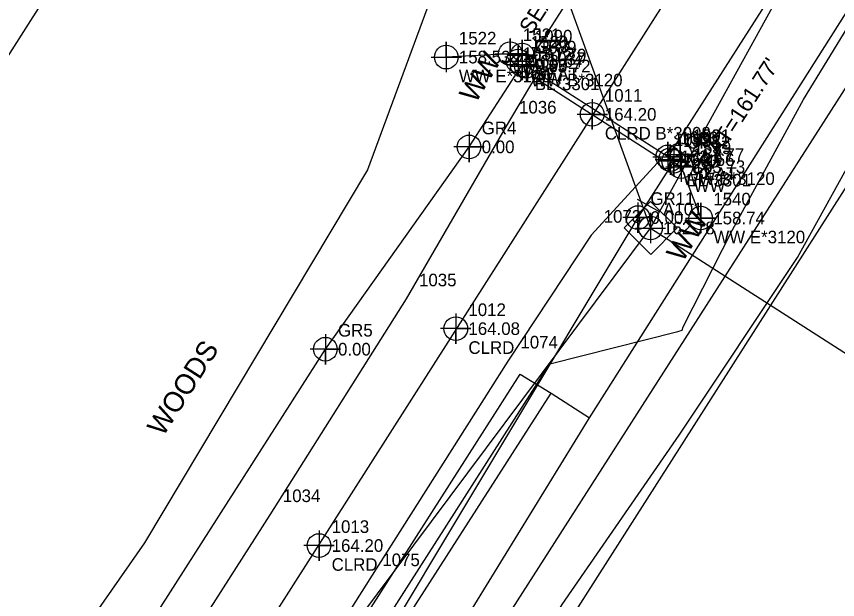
# Model space of a CAD drawing. Extents: x 1840200 to 1849051, y 348278 to 353012.
# Drawn here: x 1844547 to 1844709.8, y 350604.9 to 350720.4 of the extents above; entities that cross this region are included whole.
import ezdxf

# ---------------------------------------------------------------- set-up
doc = ezdxf.new("R2010")
doc.units = 0
for name, color, linetype in [('Cogo Default Point CELL', 7, 'Continuous'), ('COGO Default Point Elevation', 7, 'Continuous'), ('COGO Default Point Number', 7, 'Continuous'), ('CTL Supplemental Horizontal and Vertical CELL', 7, 'Continuous'), ('Exist DTM Crownline Cogo Comment', 7, 'Continuous'), ('Exist DTM Crownline Cogo Elevation', 7, 'Continuous'), ('Exist DTM Crownline Cogo Number', 7, 'Continuous'), ('Exist DTM Crownline Cogo Point CELL', 7, 'Continuous'), ('Exist Guardrail', 7, 'Continuous'), ('Exist Guardrail Cogo Comment', 7, 'Continuous'), ('Exist Guardrail Cogo Elevation', 7, 'Continuous'), ('Exist Guardrail Cogo Number', 7, 'Continuous'), ('Exist Guardrail Cogo Point CELL', 7, 'Continuous'), ('Exist Horizontal Alignment', 7, 'Continuous'), ('Exist Horizontal Baseline Alignment', 7, 'Continuous'), ('Exist Horizontal Baseline Alignment Station Label', 7, 'Continuous'), ('Exist Horizontal Baseline Alignment Tick small', 7, 'Continuous'), ('Exist Horizontal T-Line Alignment', 7, 'Continuous'), ('Exist Right of Way Line', 7, 'Continuous'), ('Exist Roads EOP', 7, 'Continuous'), ('Exist Roads EOP Cogo Number', 7, 'Continuous'), ('Exist Structure Major Bridge Seat Cogo Comment', 7, 'Continuous'), ('Exist Structure Major Bridge Seat Cogo Elevation', 7, 'Continuous'), ('Exist Structure Major Bridge Seat Cogo Number', 7, 'Continuous'), ('Exist Structure Major Bridge Seat Cogo Point CELL', 7, 'Continuous'), ('Exist Structure Major Bridge Seat Top Elevation', 7, 'Continuous'), ('Exist Structure Major Deck Tunnel Box Culvert', 7, 'Continuous'), ('Exist Structure Major Deck Tunnel Box Culvert Cogo Elevation', 7, 'Continuous'), ('Exist Structure Major Deck Tunnel Box Culvert Cogo Number', 7, 'Continuous'), ('Exist Structure Major Deck Tunnel Box Culvert Cogo Point CELL', 7, 'Continuous'), ('Exist Structure Minor Head and End Wall', 7, 'Continuous'), ('Exist Structure Minor Head and End Wall Cogo Comment', 7, 'Continuous'), ('Exist Structure Minor Head and End Wall Cogo Elevation', 7, 'Continuous'), ('Exist Structure Minor Head and End Wall Cogo Number', 7, 'Continuous'), ('Exist Structure Minor Head and End Wall Cogo Point CELL', 7, 'Continuous'), ('Exist Structure Minor Head and End Wall Text', 7, 'Continuous'), ('Exist Utilities Telephone UG Cable', 7, 'Continuous'), ('Exist Utilities Water UG Line SUE', 7, 'Continuous'), ('Exist Vegetation Woods Line', 7, 'Continuous'), ('Exist Vegetation Woods Line Text', 7, 'Continuous')]:
    doc.layers.add(name, color=color, linetype=linetype)

# ---------------------------------------------------------------- blocks, each defined once
blk = doc.blocks.new('EXIST DTM CROWNLINE COGO POINT')
at = {"layer": 'Exist DTM Crownline Cogo Point CELL'}
blk.add_lwpolyline([(0, 0.06), (0, -0.06), (0, 0), (0.06, 0), (-0.06, 0)], dxfattribs=at)
blk.add_circle((0, 0), 0.0469, dxfattribs=at)
blk = doc.blocks.new('EXIST STRUCTURE MAJOR BRIDGE SEAT COGO POINT')
at = {"layer": 'Exist Structure Major Bridge Seat Cogo Point CELL'}
blk.add_lwpolyline([(-0.06, 0), (0.06, 0), (0, 0), (0, 0.06), (0, -0.06)], dxfattribs=at)
blk.add_circle((0, 0), 0.0469, dxfattribs=at)
blk = doc.blocks.new('EXIST STRUCTURE MINOR HEAD AND END WALL COGO POINT')
at = {"layer": 'Exist Structure Minor Head and End Wall Cogo Point CELL'}
blk.add_lwpolyline([(-0.06, 0), (0.06, 0), (0, 0), (0, 0.06), (0, -0.06)], dxfattribs=at)
blk.add_circle((0, 0), 0.0469, dxfattribs=at)
blk = doc.blocks.new('EXIST STRUCTURE MAJOR DECK TUNNEL BOX CULVERT COGO POINT')
at = {"layer": 'Exist Structure Major Deck Tunnel Box Culvert Cogo Point CELL'}
blk.add_lwpolyline([(-0.06, 0), (0.06, 0), (0, 0), (0, 0.06), (0, -0.06)], dxfattribs=at)
blk.add_circle((0, 0), 0.0469, dxfattribs=at)
blk = doc.blocks.new('COGO DEFAULT POINT')
at = {"layer": 'Cogo Default Point CELL'}
for points in [[(0, 0.06), (0, 0)], [(-0.06, 0), (0, 0)], [(0, 0), (0.06, 0)], [(0, 0), (0, -0.06)]]:
    blk.add_lwpolyline(points, dxfattribs=at)
blk.add_circle((0, 0), 0.0469, dxfattribs=at)

msp = doc.modelspace()

# ---------------------------------------------------------------- linework, layer by layer
at = {"layer": 'CTL Supplemental Horizontal and Vertical CELL'}
msp.add_line((1844672.71, 350678.49), (1844672.71, 350678.49), dxfattribs=at)
msp.add_lwpolyline([(1844667.5, 350678.51), (1844672.74, 350683.75), (1844677.99, 350678.5), (1844672.75, 350673.26)], close=True, dxfattribs=at)
at = {"layer": 'Exist Guardrail'}
for points in [[(1844472.68, 350444.35), (1844517.09, 350511.9), (1844608.27, 350654.48), (1844636.75, 350694.56), (1844647.28, 350710.8)], [(1844677.31, 350691.72), (1844670.2, 350680.56), (1844613.75, 350586.56), (1844534.96, 350463.6), (1844508.35, 350421.22)]]:
    msp.add_lwpolyline(points, dxfattribs=at)
at = {"layer": 'Exist Guardrail Cogo Point CELL'}
for points in [[(1844647.28, 350713.8), (1844647.28, 350707.8), (1844647.28, 350710.8), (1844650.28, 350710.8), (1844644.28, 350710.8)], [(1844636.75, 350697.56), (1844636.75, 350691.56), (1844636.75, 350694.56), (1844639.75, 350694.56), (1844633.75, 350694.56)], [(1844677.31, 350694.72), (1844677.31, 350688.72), (1844677.31, 350691.72), (1844680.31, 350691.72), (1844674.31, 350691.72)], [(1844670.2, 350683.56), (1844670.2, 350677.56), (1844670.2, 350680.56), (1844673.2, 350680.56), (1844667.2, 350680.56)], [(1844608.27, 350657.48), (1844608.27, 350651.48), (1844608.27, 350654.48), (1844611.27, 350654.48), (1844605.27, 350654.48)]]:
    msp.add_lwpolyline(points, dxfattribs=at)
for centre in [(1844647.28, 350710.8), (1844636.75, 350694.56), (1844677.31, 350691.72), (1844670.2, 350680.56), (1844608.27, 350654.48)]:
    msp.add_circle(centre, 2.34, dxfattribs=at)
at = {"layer": 'Exist Horizontal Alignment'}
msp.add_line((1844418.91, 350320.78), (1844832.24, 350969.01), dxfattribs=at)
at = {"layer": 'Exist Horizontal Baseline Alignment'}
for p, q in [((1844672.71, 350678.49), (1845002.14, 351275.18)), ((1844196.06, 350040.59), (1844672.71, 350678.49))]:
    msp.add_line(p, q, dxfattribs=at)
at = {"layer": 'Exist Horizontal Baseline Alignment Station Label'}
msp.add_line((1844672.71, 350678.49), (1844914.65, 350523.26), dxfattribs=at)
at = {"layer": 'Exist Horizontal Baseline Alignment Tick small'}
msp.add_line((1844674.5, 350681.72), (1844670.12, 350684.14), dxfattribs=at)
at = {"layer": 'Exist Horizontal T-Line Alignment'}
msp.add_line((1844614.74, 350838), (1844672.71, 350678.49), dxfattribs=at)
at = {"layer": 'Exist Right of Way Line'}
for p, q in [((1844331.22, 350376.7), (1844744.55, 351024.92)), ((1844461.07, 350293.9), (1844874.4, 350942.13))]:
    msp.add_line(p, q, dxfattribs=at)
at = {"layer": 'Exist Roads EOP'}
for points in [[(1844317.31, 350184.26), (1844345.69, 350228.47), (1844373.13, 350270.92), (1844400.53, 350313.92), (1844428.29, 350357.34), (1844456.44, 350401.43), (1844484.95, 350446.26), (1844513.17, 350490.7), (1844540.9, 350534.15), (1844569.09, 350577.53), (1844597.34, 350621.69), (1844624.33, 350664.44), (1844644.15, 350698.67), (1844649.87, 350708.27)], [(1844649.87, 350708.27), (1844674.83, 350692.21)], [(1844674.83, 350692.21), (1844660.93, 350677.04), (1844644.43, 350652.12), (1844617.05, 350609), (1844589.15, 350564.8), (1844561.53, 350522), (1844533.59, 350478.19), (1844505.27, 350433.81), (1844476.6, 350389.11), (1844448.52, 350344.88), (1844420.88, 350301.62), (1844392.87, 350258.29), (1844365.83, 350215.59), (1844337.76, 350171.55)]]:
    msp.add_lwpolyline(points, dxfattribs=at)
at = {"layer": 'Exist Structure Major Deck Tunnel Box Culvert'}
msp.add_lwpolyline([(1844648.1, 350710.56), (1844734.92, 350846.55), (1844763.11, 350828.55), (1844676.15, 350692.59), (1844648.1, 350710.56)], dxfattribs=at)
at = {"layer": 'Exist Structure Minor Head and End Wall'}
for points in [[(1844646.46, 350711.55), (1844644.91, 350713.02), (1844632.23, 350712.35)], [(1844676.63, 350692.03), (1844678.76, 350690.64), (1844682.66, 350680.46)]]:
    msp.add_lwpolyline(points, dxfattribs=at)
at = {"layer": 'Exist Utilities Telephone UG Cable'}
for points in [[(1844346.44, 350151.45), (1844341.26, 350155.73), (1844478.11, 350373.12), (1844653.01, 350645.77), (1844660.65, 350640.87), (1844715.71, 350727.83), (1844785.54, 350833.66), (1844790.43, 350842.4), (1844781.52, 350847.91), (1844890.71, 351011.88), (1845027.38, 351230.56), (1845029.36, 351233.76), (1845056.36, 351221.55), (1845032.73, 351239.39), (1845066.03, 351291.24)], [(1844331.53, 350112.62), (1844354.74, 350149.21), (1844815.08, 350868.27), (1844864.7, 350947.73), (1845038.47, 351224.2), (1845056.36, 351221.55), (1845046.68, 351237.02), (1845077.41, 351286.63)], [(1844346.44, 350151.45), (1844350.06, 350157.58), (1844340.13, 350164.26), (1844370.54, 350213.64), (1844434.34, 350316.06), (1844545.77, 350491.33), (1844646.87, 350649.54), (1844653.01, 350645.77)], [(1844346.44, 350151.45), (1844352.66, 350151.55), (1844626.53, 350585.44), (1844660.65, 350640.87)]]:
    msp.add_lwpolyline(points, dxfattribs=at)
at = {"layer": 'Exist Utilities Water UG Line SUE'}
msp.add_lwpolyline([(1844615.42, 350593.11), (1844652.79, 350651.56), (1844678.12, 350657.97), (1844679, 350658.28), (1844679.2, 350658.91), (1844688.96, 350678.16), (1844703.02, 350703.95), (1844712.42, 350719.28), (1844723.85, 350736.18), (1844772.75, 350811.52), (1844793.33, 350839.86), (1844806.55, 350860.02), (1844807.89, 350862.26), (1844812.47, 350868.84), (1844812.76, 350869.4), (1844812.25, 350870.1), (1844806.09, 350891.76), (1844805.98, 350892.36), (1844806.31, 350893.29), (1844818.47, 350912.44), (1844840.28, 350944.51), (1844863.37, 350979.98)], dxfattribs=at)
at = {"layer": 'Exist Vegetation Woods Line'}
for points in [[(1844630.57, 350740.37), (1844632.87, 350734.09), (1844616.63, 350690.01)], [(1844678.39, 350637.45), (1844701.84, 350672.62), (1844731.38, 350726.16), (1844740.11, 350728.19), (1844752.45, 350719.33), (1844754.26, 350696.1), (1844743.49, 350668.1), (1844718.2, 350612.08)], [(1844616.63, 350690.01), (1844572.44, 350616.14), (1844513.95, 350532.41), (1844449.49, 350471.85), (1844374.19, 350416.85), (1844306.59, 350358.49), (1844270.69, 350319.29), (1844210.03, 350256.61), (1844143.34, 350211.7), (1844104.77, 350184.58), (1844095.43, 350186.87), (1844080.51, 350200.35), (1844071.84, 350234.77)], [(1844718.2, 350612.08), (1844710.95, 350599.86), (1844703.14, 350586.68), (1844690.5, 350571.97), (1844672.6, 350567.46), (1844655.09, 350566.19), (1844645.73, 350562), (1844631.72, 350562.62), (1844644.55, 350585.95), (1844655.19, 350603.89), (1844678.39, 350637.45)]]:
    msp.add_lwpolyline(points, dxfattribs=at)

# ---------------------------------------------------------------- block references
at = {"layer": 'Cogo Default Point CELL', "xscale": 50, "yscale": 50}
msp.add_blockref('COGO DEFAULT POINT', (1844672.71, 350678.49), dxfattribs=at)
at = {"layer": 'Exist DTM Crownline Cogo Point CELL', "xscale": 50, "yscale": 50}
for p in [(1844661.16, 350701.01), (1844634.12, 350658.55), (1844607.01, 350615.58)]:
    msp.add_blockref('EXIST DTM CROWNLINE COGO POINT', p, dxfattribs=at)
at = {"layer": 'Exist Structure Major Bridge Seat Cogo Point CELL', "xscale": 50, "yscale": 50}
for p in [(1844647.29, 350712.75), (1844678.57, 350693.03)]:
    msp.add_blockref('EXIST STRUCTURE MAJOR BRIDGE SEAT COGO POINT', p, dxfattribs=at)
at = {"layer": 'Exist Structure Major Deck Tunnel Box Culvert Cogo Point CELL', "xscale": 50, "yscale": 50}
for p in [(1844648.1, 350710.56), (1844676.15, 350692.59)]:
    msp.add_blockref('EXIST STRUCTURE MAJOR DECK TUNNEL BOX CULVERT COGO POINT', p, dxfattribs=at)
at = {"layer": 'Exist Structure Minor Head and End Wall Cogo Point CELL', "xscale": 50, "yscale": 50}
for p in [(1844644.91, 350713.02), (1844632.23, 350712.35), (1844646.46, 350711.55), (1844676.63, 350692.03), (1844678.76, 350690.64), (1844682.66, 350680.46)]:
    msp.add_blockref('EXIST STRUCTURE MINOR HEAD AND END WALL COGO POINT', p, dxfattribs=at)

# ---------------------------------------------------------------- texts
at = {"layer": 'COGO Default Point Elevation'}
msp.add_text('162.78', height=2.5, dxfattribs=at).set_placement((1844675.21, 350677.24))
at = {"layer": 'COGO Default Point Number'}
msp.add_text('A101', height=2.5, dxfattribs=at).set_placement((1844675.21, 350680.99))
at = {"layer": 'Exist DTM Crownline Cogo Comment'}
for s, p in [('CLRD B*3008', (1844663.66, 350696.01)), ('CLRD', (1844636.62, 350653.55)), ('CLRD', (1844609.51, 350610.58))]:
    msp.add_text(s, height=2.5, dxfattribs=at).set_placement(p)
at = {"layer": 'Exist DTM Crownline Cogo Elevation'}
for s, p in [('164.20', (1844663.66, 350699.76)), ('164.08', (1844636.62, 350657.3)), ('164.20', (1844609.51, 350614.33))]:
    msp.add_text(s, height=2.5, dxfattribs=at).set_placement(p)
at = {"layer": 'Exist DTM Crownline Cogo Number'}
for s, p in [('1011', (1844663.66, 350703.51)), ('1012', (1844636.62, 350661.05)), ('1013', (1844609.51, 350618.08))]:
    msp.add_text(s, height=2.5, dxfattribs=at).set_placement(p)
at = {"layer": 'Exist Guardrail Cogo Comment'}
for s, p in [('BL*3301', (1844649.78, 350705.8)), ('EL*3301', (1844679.81, 350686.72))]:
    msp.add_text(s, height=2.5, dxfattribs=at).set_placement(p)
at = {"layer": 'Exist Guardrail Cogo Elevation'}
for p in [(1844649.78, 350709.55), (1844639.25, 350693.31), (1844679.81, 350690.47), (1844672.7, 350679.31), (1844610.77, 350653.23)]:
    msp.add_text('0.00', height=2.5, dxfattribs=at).set_placement(p)
at = {"layer": 'Exist Guardrail Cogo Number'}
for s, p in [('GR3', (1844649.78, 350713.3)), ('GR4', (1844639.25, 350697.06)), ('GR12', (1844679.81, 350694.22)), ('GR11', (1844672.7, 350683.06)), ('GR5', (1844610.77, 350656.98))]:
    msp.add_text(s, height=2.5, dxfattribs=at).set_placement(p)
at = {"layer": 'Exist Roads EOP Cogo Number'}
for s, p in [('1037', (1844652.37, 350710.77)), ('1036', (1844646.65, 350701.17)), ('1072', (1844677.33, 350694.71)), ('1073', (1844663.43, 350679.54)), ('1035', (1844626.83, 350666.94)), ('1074', (1844646.93, 350654.62)), ('1034', (1844599.84, 350624.19)), ('1075', (1844619.55, 350611.5))]:
    msp.add_text(s, height=2.5, dxfattribs=at).set_placement(p)
at = {"layer": 'Exist Structure Major Bridge Seat Cogo Comment'}
for p in [(1844649.79, 350707.75), (1844681.07, 350688.03)]:
    msp.add_text('SEAT', height=2.5, dxfattribs=at).set_placement(p)
at = {"layer": 'Exist Structure Major Bridge Seat Cogo Elevation'}
for s, p in [('161.79', (1844649.79, 350711.5)), ('161.77', (1844681.07, 350691.78))]:
    msp.add_text(s, height=2.5, dxfattribs=at).set_placement(p)
at = {"layer": 'Exist Structure Major Bridge Seat Cogo Number'}
for s, p in [('1090', (1844649.79, 350715.25)), ('1091', (1844681.07, 350695.53))]:
    msp.add_text(s, height=2.5, dxfattribs=at).set_placement(p)
at = {"layer": 'Exist Structure Major Bridge Seat Top Elevation'}
for s, rotation, p in [("SEAT=161.79'", 57.3954, (1844649.16, 350716.61)), ("SEAT=161.77'", 56.9418, (1844683.34, 350687.7))]:
    msp.add_text(s, height=3.2, rotation=rotation, dxfattribs=at).set_placement(p)
at = {"layer": 'Exist Structure Major Deck Tunnel Box Culvert Cogo Elevation'}
for s, p in [('163.72', (1844650.6, 350709.31)), ('163.67', (1844678.65, 350691.34))]:
    msp.add_text(s, height=2.5, dxfattribs=at).set_placement(p)
at = {"layer": 'Exist Structure Major Deck Tunnel Box Culvert Cogo Number'}
for s, p in [('1089', (1844650.6, 350713.06)), ('1086', (1844678.65, 350695.09))]:
    msp.add_text(s, height=2.5, dxfattribs=at).set_placement(p)
at = {"layer": 'Exist Structure Minor Head and End Wall Cogo Comment'}
for s, p in [('WW E*3120', (1844634.73, 350707.35)), ('WW', (1844647.41, 350708.02)), ('WW B*3120', (1844648.96, 350706.55)), ('WW B*3120', (1844679.13, 350687.03)), ('WW', (1844681.26, 350685.64)), ('WW E*3120', (1844685.16, 350675.46))]:
    msp.add_text(s, height=2.5, dxfattribs=at).set_placement(p)
at = {"layer": 'Exist Structure Minor Head and End Wall Cogo Elevation'}
for s, p in [('163.72', (1844647.41, 350711.77)), ('158.53', (1844634.73, 350711.1)), ('163.64', (1844648.96, 350710.3)), ('163.66', (1844679.13, 350690.78)), ('163.73', (1844681.26, 350689.39)), ('158.74', (1844685.16, 350679.21))]:
    msp.add_text(s, height=2.5, dxfattribs=at).set_placement(p)
at = {"layer": 'Exist Structure Minor Head and End Wall Cogo Number'}
for s, p in [('1522', (1844634.73, 350714.85)), ('1521', (1844647.41, 350715.52)), ('1520', (1844648.96, 350714.05)), ('1538', (1844679.13, 350694.53)), ('1539', (1844681.26, 350693.14)), ('1540', (1844685.16, 350682.96))]:
    msp.add_text(s, height=2.5, dxfattribs=at).set_placement(p)
at = {"layer": 'Exist Structure Minor Head and End Wall Text'}
for p in [(1844638.04, 350703.03), (1844679.08, 350671.52)]:
    msp.add_text('WW', height=4, rotation=59.0825, dxfattribs=at).set_placement(p)
at = {"layer": 'Exist Vegetation Woods Line Text'}
msp.add_text('WOODS', height=4, rotation=57.4041, dxfattribs=at).set_placement((1844576.09, 350637))

doc.saveas('drawing.dxf')
